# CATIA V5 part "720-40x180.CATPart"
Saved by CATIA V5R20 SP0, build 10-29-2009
Part number: 720-40x180
Definition: NONE
Nomenclature: 720-40x180
Source: Unknown
Description: 720-40x180
Bounding box of the stored display mesh (mm): x 0 to 180, y -20 to 20, z -20 to 20
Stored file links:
  C:\Users\Utente\Desktop\IO LAVORO\3D X SITO CF\X SITO\720\720-40x180.CATPart

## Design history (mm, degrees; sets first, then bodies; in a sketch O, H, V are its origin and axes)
Body1 "720-40x180" (main body)
  Solid1: solid without history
